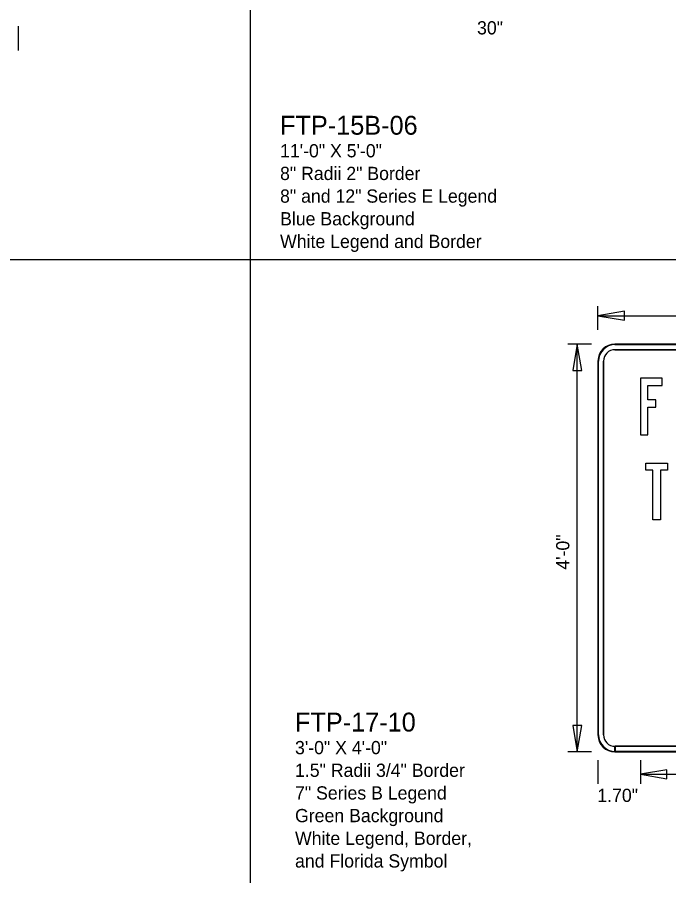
# Model space of a CAD drawing. Extents: x 0 to 770, y 0 to 495.
# Drawn here: x 205.8 to 378.2, y 0 to 229.1 of the extents above; entities that cross this region are included whole.
import ezdxf

# ---------------------------------------------------------------- set-up
doc = ezdxf.new("R2010")
doc.units = 0
for name, color, linetype in [('Default', 7, 'Continuous'), ('Dimension', 7, 'Continuous'), ('GSBWFill', 7, 'Continuous'), ('GSColorFill', 7, 'Continuous'), ('GSDims', 7, 'Continuous'), ('GSOutline', 7, 'Continuous'), ('SheetLines_dp', 7, 'Continuous')]:
    doc.layers.add(name, color=color, linetype=linetype)

msp = doc.modelspace()

# ---------------------------------------------------------------- linework, layer by layer
at = {"layer": 'Dimension'}
for points in [[(359.47, 150.12), (366.48, 148.93), (366.48, 151.31)], [(353.97, 142.62), (352.78, 135.61), (355.16, 135.61)], [(353.97, 34.62), (355.16, 41.64), (352.78, 41.64)], [(370.72, 28.7), (377.73, 27.51), (377.73, 29.88)]]:
    msp.add_lwpolyline(points, close=True, dxfattribs=at)
at = {"layer": 'GSBWFill'}
for p, q in [((444.97, 142.62), (363.97, 142.62)), ((363.97, 141.12), (444.97, 141.12)), ((359.47, 138.12), (359.47, 39.12)), ((360.97, 39.12), (360.97, 138.12)), ((363.97, 34.62), (363.97, 36.12)), ((444.97, 36.12), (363.98, 36.12)), ((363.98, 36.12), (363.98, 34.62)), ((363.98, 34.62), (444.97, 34.62))]:
    msp.add_line(p, q, dxfattribs=at)
for points in [[(372.67, 118.62), (372.67, 125.9), (374.77, 125.9), (374.77, 127.85), (372.67, 127.85), (372.67, 131.67), (376.42, 131.67), (376.42, 133.62), (370.72, 133.62), (370.72, 118.62)], [(377.84, 109.25), (375.97, 109.25), (375.97, 96.12), (374.02, 96.12), (374.02, 109.25), (372.14, 109.25), (372.14, 111.12), (377.84, 111.12)]]:
    msp.add_lwpolyline(points, close=True, dxfattribs=at)
for centre, radius, start, end in [((363.97, 138.12), 4.5, 90, 180), ((363.97, 138.12), 3, 90, 180), ((363.97, 39.12), 4.5, 180, 270), ((363.97, 39.12), 3, 180, 270)]:
    msp.add_arc(centre, radius, start, end, dxfattribs=at)
at = {"layer": 'GSColorFill'}
for p, q in [((444.97, 142.62), (363.97, 142.62)), ((444.97, 142.62), (363.97, 142.62)), ((444.97, 142.62), (363.97, 142.62)), ((363.97, 142.47), (444.97, 142.47)), ((363.97, 141.12), (444.97, 141.12)), ((359.47, 138.12), (359.47, 39.12)), ((359.47, 138.12), (359.47, 39.12)), ((359.47, 138.12), (359.47, 39.12)), ((359.62, 39.12), (359.62, 138.12)), ((360.97, 39.12), (360.97, 138.12)), ((363.97, 34.62), (363.97, 36.12)), ((363.97, 34.62), (363.97, 34.77)), ((444.97, 34.77), (363.97, 34.77)), ((363.97, 34.77), (363.97, 34.62)), ((363.97, 34.62), (444.97, 34.62)), ((363.97, 34.62), (444.97, 34.62)), ((444.97, 36.12), (363.98, 36.12)), ((363.98, 36.12), (363.98, 34.62)), ((363.98, 34.62), (444.97, 34.62))]:
    msp.add_line(p, q, dxfattribs=at)
for points in [[(372.67, 118.62), (372.67, 125.9), (374.77, 125.9), (374.77, 127.85), (372.67, 127.85), (372.67, 131.67), (376.42, 131.67), (376.42, 133.62), (370.72, 133.62), (370.72, 118.62)], [(377.84, 109.25), (375.97, 109.25), (375.97, 96.12), (374.02, 96.12), (374.02, 109.25), (372.14, 109.25), (372.14, 111.12), (377.84, 111.12)]]:
    msp.add_lwpolyline(points, close=True, dxfattribs=at)
for centre, radius, start, end in [((363.97, 138.12), 4.5, 90, 180), ((363.97, 138.12), 4.5, 90, 180), ((363.97, 138.12), 4.5, 90, 180), ((363.97, 138.12), 4.35, 90, 180), ((363.97, 138.12), 3, 90, 180), ((363.97, 39.12), 4.5, 180, 270), ((363.97, 39.12), 4.5, 180, 270), ((363.97, 39.12), 4.5, 180, 270), ((363.97, 39.12), 4.35, 180, 270), ((363.97, 39.12), 3, 180, 270)]:
    msp.add_arc(centre, radius, start, end, dxfattribs=at)
at = {"layer": 'GSDims'}
for p, q in [((205.98, 226.83), (205.98, 220.36)), ((359.47, 146.37), (359.47, 152.62)), ((359.47, 150.12), (449.47, 150.12)), ((357.72, 142.62), (351.47, 142.62)), ((353.97, 34.62), (353.97, 142.62)), ((357.72, 34.62), (351.47, 34.62)), ((359.47, 32.45), (359.47, 26.2)), ((370.72, 32.45), (370.72, 26.2)), ((370.72, 28.7), (438.22, 28.7))]:
    msp.add_line(p, q, dxfattribs=at)
at = {"layer": 'GSOutline'}
for p, q in [((444.97, 142.62), (363.97, 142.62)), ((444.97, 141.12), (363.97, 141.12)), ((359.47, 138.12), (359.47, 39.12)), ((360.97, 138.12), (360.97, 39.12)), ((363.97, 36.12), (444.97, 36.12)), ((363.97, 34.62), (444.97, 34.62))]:
    msp.add_line(p, q, dxfattribs=at)
for points in [[(372.67, 118.62), (372.67, 125.9), (374.77, 125.9), (374.77, 127.85), (372.67, 127.85), (372.67, 131.67), (376.42, 131.67), (376.42, 133.62), (370.72, 133.62), (370.72, 118.62)], [(377.84, 109.25), (375.97, 109.25), (375.97, 96.12), (374.02, 96.12), (374.02, 109.25), (372.14, 109.25), (372.14, 111.12), (377.84, 111.12)]]:
    msp.add_lwpolyline(points, close=True, dxfattribs=at)
for centre, radius, start, end in [((363.97, 138.12), 4.5, 90, 180), ((363.97, 138.12), 3, 90, 180), ((363.97, 39.12), 4.5, 180, 270), ((363.97, 39.12), 3, 180, 270)]:
    msp.add_arc(centre, radius, start, end, dxfattribs=at)
at = {"layer": 'SheetLines_dp'}
for p, q in [((267.49, 0), (267.49, 330)), ((0, 165), (770, 165))]:
    msp.add_line(p, q, dxfattribs=at)

# ---------------------------------------------------------------- texts
at = {"layer": 'Default'}
for s, height, p in [('30"', 3.5, (327.46, 224.6)), ('FTP-15B-06', 5, (275.32, 198.05)), ('11\'-0" X 5\'-0"', 3.5, (275.32, 192.05)), ('8" Radii 2" Border', 3.5, (275.32, 186.05)), ('8" and 12" Series E Legend', 3.5, (275.32, 180.05)), ('Blue Background', 3.5, (275.32, 174.05)), ('White Legend and Border', 3.5, (275.32, 168.05)), ('FTP-17-10', 5, (279.28, 40.02)), ('3\'-0" X 4\'-0"', 3.5, (279.28, 34.02)), ('1.5" Radii 3/4" Border', 3.5, (279.28, 28.02)), ('7" Series B Legend', 3.5, (279.28, 22.02)), ('Green Background', 3.5, (279.28, 16.02)), ('White Legend, Border, ', 3.5, (279.28, 10.02)), ('and Florida Symbol', 3.5, (279.28, 4.02))]:
    msp.add_text(s, height=height, dxfattribs=at).set_placement(p)
at = {"layer": 'GSDims'}
msp.add_text('4\'-0"', height=3.5, rotation=90, dxfattribs=at).set_placement((351.89, 82.88))
msp.add_text('1.70"', height=3.5, dxfattribs=at).set_placement((359.29, 21.38))

doc.saveas('drawing.dxf')
